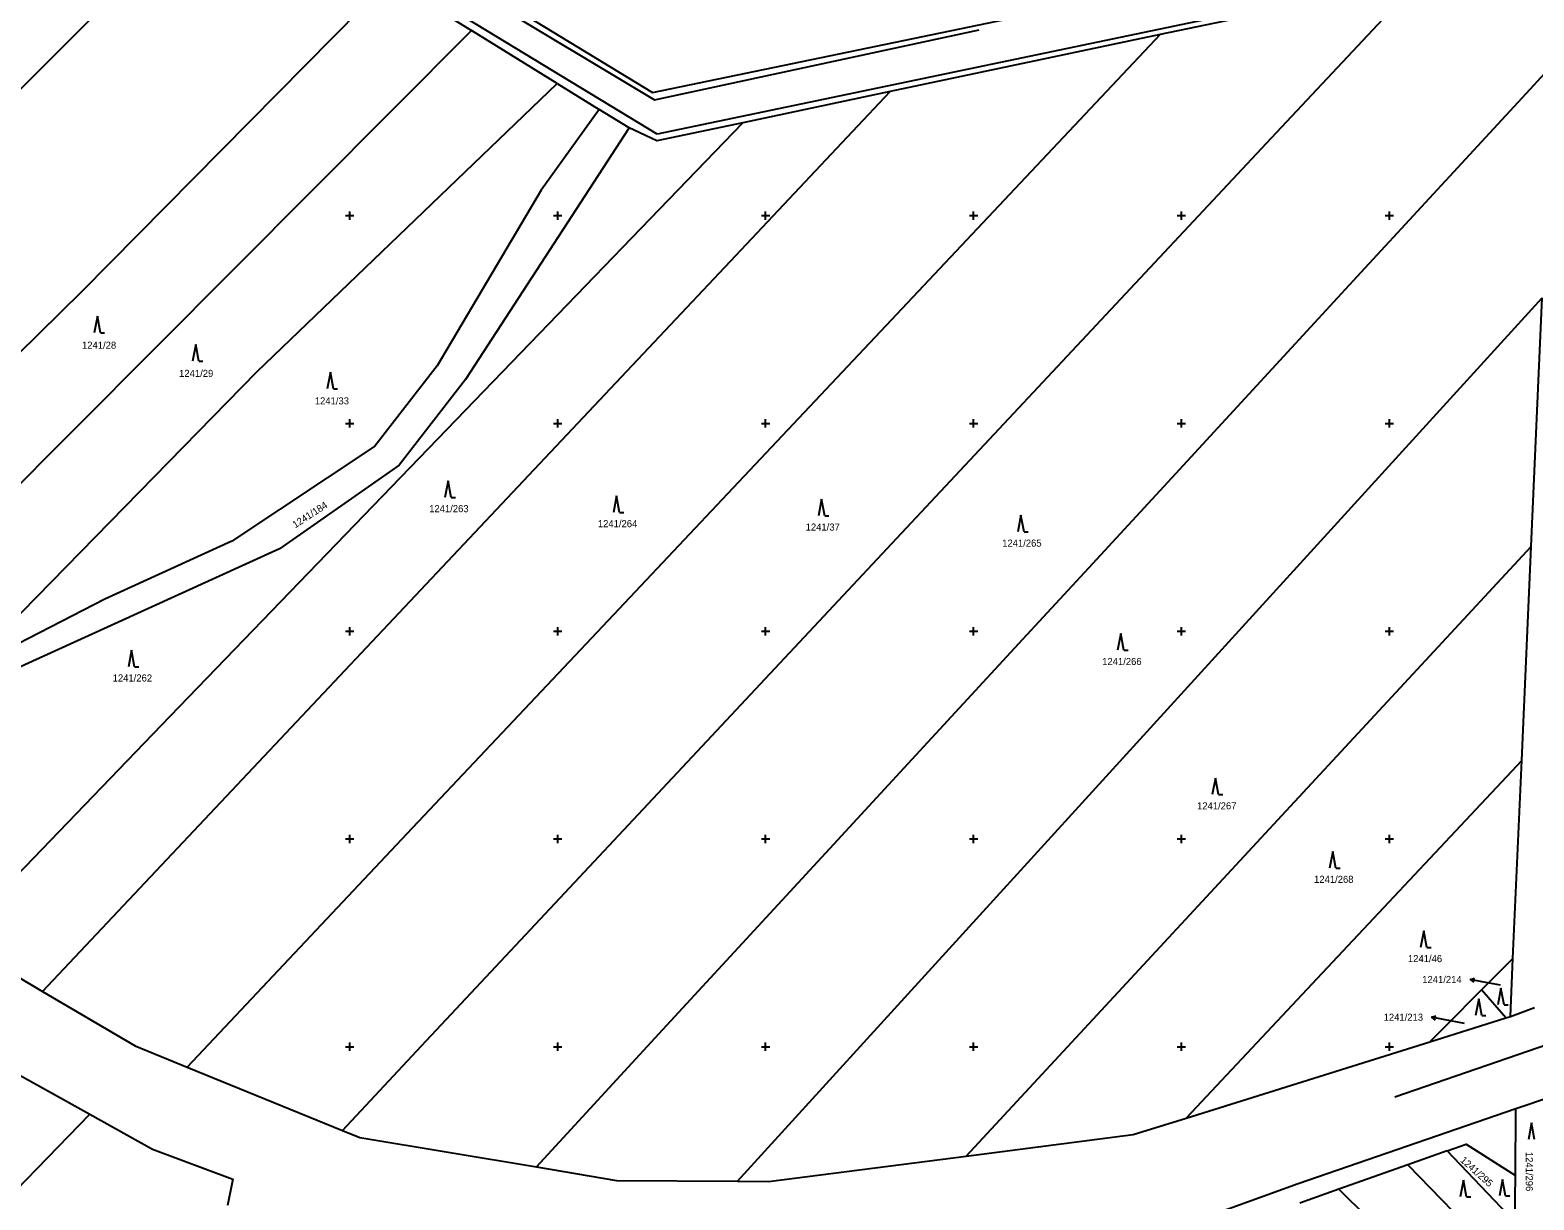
# Model space of a CAD drawing. Extents: x -776734 to -748832, y -1118122 to -976986.
# Drawn here: x -751976.9 to -751615.2, y -1114886.9 to -1114605.4 of the extents above; entities that cross this region are included whole.
import ezdxf

# ---------------------------------------------------------------- set-up
doc = ezdxf.new("R2010")
doc.units = 0
for name, color, linetype in [('KM_Hranice parcel', 7, 'Continuous'), ('KM_Parcelní čísla', 7, 'Continuous'), ('KM_Pop  PČ popisy', 7, 'Continuous'), ('KM_Vnitřní kresba', 7, 'Continuous'), ('KM_Značky kultur', 7, 'Continuous'), ('Level 61 Křížky', 7, 'Continuous'), ('OSA', 7, 'Continuous')]:
    doc.layers.add(name, color=color, linetype=linetype)

msp = doc.modelspace()

# ---------------------------------------------------------------- linework, layer by layer
at = {"layer": 'KM_Hranice parcel'}
for p, q in [((-751890.47, -1114593.24), (-751870.77, -1114605.44)), ((-751642.03, -1114593.16), (-751705.11, -1114606.47)), ((-751870.77, -1114605.44), (-752034.81, -1114770.36)), ((-751850.14, -1114618.21), (-751870.77, -1114605.44)), ((-751705.11, -1114606.47), (-751770.02, -1114620.17)), ((-751850.14, -1114618.21), (-751840, -1114624.49)), ((-751770.02, -1114620.17), (-751805.49, -1114627.66)), ((-751832.84, -1114628.92), (-751840, -1114624.49)), ((-751615.92, -1114729.62), (-751613.29, -1114669.83)), ((-751618.19, -1114781.14), (-751615.92, -1114729.62)), ((-751958.9, -1114742.29), (-751992.96, -1114759.81)), ((-751620.28, -1114828.72), (-751618.19, -1114781.14)), ((-751627.87, -1114836.32), (-751620.28, -1114828.72)), ((-751620.9, -1114842.7), (-751620.28, -1114828.72)), ((-751622.03, -1114843.06), (-751627.87, -1114836.32)), ((-751640.29, -1114848.78), (-751622.03, -1114843.06)), ((-751622.03, -1114843.06), (-751620.9, -1114842.7)), ((-751620.9, -1114842.7), (-751615.07, -1114840.52)), ((-751698.88, -1114867.14), (-751640.29, -1114848.78)), ((-751939.11, -1114854.9), (-751901.76, -1114870.11)), ((-751619.71, -1114880.94), (-751619.58, -1114864.94)), ((-751611.28, -1114862.12), (-751619.58, -1114864.94)), ((-751636.13, -1114875.06), (-751645.58, -1114878.41)), ((-751619.8, -1114892.13), (-751636.13, -1114875.06)), ((-751645.58, -1114878.41), (-751662.15, -1114884.29)), ((-751645.58, -1114878.41), (-751619.39, -1114905.36)), ((-751619.8, -1114892.13), (-751619.71, -1114880.94)), ((-751662.15, -1114884.29), (-751671.53, -1114887.62))]:
    msp.add_line(p, q, dxfattribs=at)
for points in [[(-751930.35, -1114570.59), (-752004.66, -1114645.11), (-752095.19, -1114732.79)], [(-751863.17, -1114598.48), (-751827.19, -1114620.41), (-751652.3, -1114584.09), (-751621.11, -1114577.93)], [(-752062.65, -1114764.92), (-751964.33, -1114668.21), (-751890.47, -1114593.24)], [(-751901.76, -1114870.11), (-751882.74, -1114849.78), (-751856.57, -1114821.81), (-751816.46, -1114778.95), (-751734.46, -1114691.3), (-751678.34, -1114631.33), (-751649.12, -1114600.1), (-751642.03, -1114593.16)], [(-751705.11, -1114606.47), (-751769.82, -1114675.17), (-751841.9, -1114751.7), (-751886.25, -1114798.78), (-751939.11, -1114854.9)], [(-751855.14, -1114878.92), (-751824.7, -1114845.88), (-751783.59, -1114801.27), (-751766.66, -1114782.9), (-751738.11, -1114751.92), (-751722.27, -1114734.73), (-751704.16, -1114715.09), (-751657.73, -1114664.7), (-751615.2, -1114618.55), (-751610.82, -1114613.8)], [(-751992.96, -1114759.81), (-751922.33, -1114687.6), (-751850.14, -1114618.21)], [(-751973.89, -1114836.66), (-751921.91, -1114781.47), (-751856.93, -1114712.47), (-751808.43, -1114660.96), (-751770.02, -1114620.17)], [(-751840, -1114624.49), (-751853.94, -1114643.88), (-751878.99, -1114686.19), (-751894, -1114705.47), (-751928.36, -1114728.38), (-751958.9, -1114742.29)], [(-751832.84, -1114628.92), (-751872.15, -1114689.48), (-751888.1, -1114710.05), (-751916.89, -1114730.17), (-751988.09, -1114762.56), (-752029.41, -1114785.67)], [(-751994.61, -1114823.76), (-751943.21, -1114770.46), (-751865.56, -1114689.94), (-751805.49, -1114627.66)], [(-751805.49, -1114627.66), (-751826.13, -1114632.01), (-751832.84, -1114628.92)], [(-751806.78, -1114882.34), (-751721.42, -1114788.59), (-751667.32, -1114729.17), (-751615.76, -1114672.55), (-751613.29, -1114669.83)], [(-751751.78, -1114876.29), (-751714.18, -1114835.71), (-751676.85, -1114795.4), (-751615.92, -1114729.62)], [(-751618.19, -1114781.14), (-751666.18, -1114832.29), (-751698.88, -1114867.14)], [(-751994.61, -1114823.76), (-751987.53, -1114828.61), (-751973.89, -1114836.66)], [(-751640.29, -1114848.78), (-751636.3, -1114844.78), (-751627.87, -1114836.32)], [(-751973.89, -1114836.66), (-751951.65, -1114849.8), (-751939.11, -1114854.9)], [(-751995.98, -1114846.36), (-751983.87, -1114854.34), (-751962.52, -1114866.24)], [(-751619.58, -1114864.94), (-751671.94, -1114882.94), (-751717.81, -1114899.58), (-751754.97, -1114906.02), (-751784.43, -1114907.15), (-751843.55, -1114904.34), (-751858.89, -1114907.41)], [(-752071.79, -1114978.8), (-752018.24, -1114923.64), (-751962.52, -1114866.24)], [(-751962.52, -1114866.24), (-751947.48, -1114874.63), (-751928.13, -1114881.84), (-751929.4, -1114888.2)], [(-751751.78, -1114876.29), (-751711.61, -1114871.13), (-751698.88, -1114867.14)], [(-751901.76, -1114870.11), (-751897.6, -1114871.8), (-751855.14, -1114878.92)], [(-751806.78, -1114882.34), (-751799.31, -1114882.39), (-751751.78, -1114876.29)], [(-751636.13, -1114875.06), (-751631.51, -1114873.41), (-751619.71, -1114880.94)], [(-751855.14, -1114878.92), (-751835.87, -1114882.14), (-751806.78, -1114882.34)], [(-751662.15, -1114884.29), (-751641.5, -1114904.68), (-751619.64, -1114926.27)]]:
    msp.add_lwpolyline(points, dxfattribs=at)
at = {"layer": 'KM_Pop  PČ popisy'}
for p, q in [((-751630.606, -1114833.787), (-751629.527, -1114833.487)), ((-751627.66, -1114834.36), (-751630.606, -1114833.787)), ((-751630.606, -1114833.787), (-751629.718, -1114834.47)), ((-751623.27, -1114835.19), (-751627.66, -1114834.36)), ((-751639.896, -1114842.877), (-751638.817, -1114842.577)), ((-751636.95, -1114843.45), (-751639.896, -1114842.877)), ((-751639.896, -1114842.877), (-751639.008, -1114843.56)), ((-751631.94, -1114844.43), (-751636.95, -1114843.45))]:
    msp.add_line(p, q, dxfattribs=at)
at = {"layer": 'KM_Vnitřní kresba'}
for p, q in [((-751910.92, -1114571.33), (-751826.76, -1114622.16)), ((-751617.1, -1114586.71), (-751826.11, -1114630.39)), ((-751826.11, -1114630.39), (-751889.85, -1114591.64)), ((-751826.76, -1114622.16), (-751748.67, -1114605.29))]:
    msp.add_line(p, q, dxfattribs=at)
at = {"layer": 'KM_Značky kultur'}
for p, q in [((-751960.71, -1114674.18), (-751961.46, -1114678.18)), ((-751959.96, -1114678.18), (-751960.71, -1114674.18)), ((-751959.96, -1114678.18), (-751958.964, -1114678.18)), ((-751937.06, -1114681.04), (-751937.81, -1114685.04)), ((-751936.31, -1114685.04), (-751937.06, -1114681.04)), ((-751936.31, -1114685.04), (-751935.314, -1114685.04)), ((-751904.67, -1114687.66), (-751905.42, -1114691.66)), ((-751903.92, -1114691.66), (-751904.67, -1114687.66)), ((-751903.92, -1114691.66), (-751902.924, -1114691.66)), ((-751876.36, -1114713.82), (-751877.11, -1114717.82)), ((-751875.61, -1114717.82), (-751876.36, -1114713.82)), ((-751875.61, -1114717.82), (-751874.614, -1114717.82)), ((-751835.87, -1114717.43), (-751836.62, -1114721.43)), ((-751835.12, -1114721.43), (-751835.87, -1114717.43)), ((-751786.54, -1114718.25), (-751787.29, -1114722.25)), ((-751785.79, -1114722.25), (-751786.54, -1114718.25)), ((-751835.12, -1114721.43), (-751834.124, -1114721.43)), ((-751785.79, -1114722.25), (-751784.794, -1114722.25)), ((-751738.61, -1114722.11), (-751739.36, -1114726.11)), ((-751737.86, -1114726.11), (-751738.61, -1114722.11)), ((-751737.86, -1114726.11), (-751736.864, -1114726.11)), ((-751714.6, -1114750.59), (-751715.35, -1114754.59)), ((-751713.85, -1114754.59), (-751714.6, -1114750.59)), ((-751952.49, -1114754.56), (-751953.24, -1114758.56)), ((-751951.74, -1114758.56), (-751952.49, -1114754.56)), ((-751713.85, -1114754.59), (-751712.854, -1114754.59)), ((-751951.74, -1114758.56), (-751950.744, -1114758.56)), ((-751691.83, -1114785.33), (-751692.58, -1114789.33)), ((-751691.08, -1114789.33), (-751691.83, -1114785.33)), ((-751691.08, -1114789.33), (-751690.084, -1114789.33)), ((-751663.62, -1114803.01), (-751664.37, -1114807.01)), ((-751662.87, -1114807.01), (-751663.62, -1114803.01)), ((-751662.87, -1114807.01), (-751661.874, -1114807.01)), ((-751641.74, -1114822.08), (-751642.49, -1114826.08)), ((-751640.99, -1114826.08), (-751641.74, -1114822.08)), ((-751640.99, -1114826.08), (-751639.994, -1114826.08)), ((-751623.18, -1114835.89), (-751623.93, -1114839.89)), ((-751622.43, -1114839.89), (-751623.18, -1114835.89)), ((-751628.53, -1114838.49), (-751629.28, -1114842.49)), ((-751627.78, -1114842.49), (-751628.53, -1114838.49)), ((-751622.43, -1114839.89), (-751621.434, -1114839.89)), ((-751627.78, -1114842.49), (-751626.784, -1114842.49)), ((-751615.83, -1114868.29), (-751616.58, -1114872.29)), ((-751615.08, -1114872.29), (-751615.83, -1114868.29)), ((-751632.2, -1114882.08), (-751632.95, -1114886.08)), ((-751631.45, -1114886.08), (-751632.2, -1114882.08)), ((-751622.79, -1114881.9), (-751623.54, -1114885.9)), ((-751622.04, -1114885.9), (-751622.79, -1114881.9)), ((-751631.45, -1114886.08), (-751630.454, -1114886.08)), ((-751622.04, -1114885.9), (-751621.044, -1114885.9))]:
    msp.add_line(p, q, dxfattribs=at)
at = {"layer": 'Level 61 Křížky'}
for p, q in [((-751901, -1114650), (-751899, -1114650)), ((-751900, -1114650), (-751900, -1114649)), ((-751900, -1114651), (-751900, -1114650)), ((-751851, -1114650), (-751849, -1114650)), ((-751850, -1114650), (-751850, -1114649)), ((-751850, -1114651), (-751850, -1114650)), ((-751801, -1114650), (-751799, -1114650)), ((-751800, -1114650), (-751800, -1114649)), ((-751800, -1114651), (-751800, -1114650)), ((-751751, -1114650), (-751749, -1114650)), ((-751750, -1114650), (-751750, -1114649)), ((-751750, -1114651), (-751750, -1114650)), ((-751701, -1114650), (-751699, -1114650)), ((-751700, -1114650), (-751700, -1114649)), ((-751700, -1114651), (-751700, -1114650)), ((-751651, -1114650), (-751649, -1114650)), ((-751650, -1114650), (-751650, -1114649)), ((-751650, -1114651), (-751650, -1114650)), ((-751900, -1114700), (-751900, -1114699)), ((-751850, -1114700), (-751850, -1114699)), ((-751800, -1114700), (-751800, -1114699)), ((-751750, -1114700), (-751750, -1114699)), ((-751700, -1114700), (-751700, -1114699)), ((-751650, -1114700), (-751650, -1114699)), ((-751901, -1114700), (-751899, -1114700)), ((-751900, -1114701), (-751900, -1114700)), ((-751851, -1114700), (-751849, -1114700)), ((-751850, -1114701), (-751850, -1114700)), ((-751801, -1114700), (-751799, -1114700)), ((-751800, -1114701), (-751800, -1114700)), ((-751751, -1114700), (-751749, -1114700)), ((-751750, -1114701), (-751750, -1114700)), ((-751701, -1114700), (-751699, -1114700)), ((-751700, -1114701), (-751700, -1114700)), ((-751651, -1114700), (-751649, -1114700)), ((-751650, -1114701), (-751650, -1114700)), ((-751900, -1114750), (-751900, -1114749)), ((-751850, -1114750), (-751850, -1114749)), ((-751800, -1114750), (-751800, -1114749)), ((-751750, -1114750), (-751750, -1114749)), ((-751700, -1114750), (-751700, -1114749)), ((-751650, -1114750), (-751650, -1114749)), ((-751901, -1114750), (-751899, -1114750)), ((-751900, -1114751), (-751900, -1114750)), ((-751851, -1114750), (-751849, -1114750)), ((-751850, -1114751), (-751850, -1114750)), ((-751801, -1114750), (-751799, -1114750)), ((-751800, -1114751), (-751800, -1114750)), ((-751751, -1114750), (-751749, -1114750)), ((-751750, -1114751), (-751750, -1114750)), ((-751701, -1114750), (-751699, -1114750)), ((-751700, -1114751), (-751700, -1114750)), ((-751651, -1114750), (-751649, -1114750)), ((-751650, -1114751), (-751650, -1114750)), ((-751901, -1114800), (-751899, -1114800)), ((-751900, -1114800), (-751900, -1114799)), ((-751900, -1114801), (-751900, -1114800)), ((-751851, -1114800), (-751849, -1114800)), ((-751850, -1114800), (-751850, -1114799)), ((-751850, -1114801), (-751850, -1114800)), ((-751801, -1114800), (-751799, -1114800)), ((-751800, -1114800), (-751800, -1114799)), ((-751800, -1114801), (-751800, -1114800)), ((-751751, -1114800), (-751749, -1114800)), ((-751750, -1114800), (-751750, -1114799)), ((-751750, -1114801), (-751750, -1114800)), ((-751701, -1114800), (-751699, -1114800)), ((-751700, -1114800), (-751700, -1114799)), ((-751700, -1114801), (-751700, -1114800)), ((-751651, -1114800), (-751649, -1114800)), ((-751650, -1114800), (-751650, -1114799)), ((-751650, -1114801), (-751650, -1114800)), ((-751901, -1114850), (-751899, -1114850)), ((-751900, -1114850), (-751900, -1114849)), ((-751900, -1114851), (-751900, -1114850)), ((-751851, -1114850), (-751849, -1114850)), ((-751850, -1114850), (-751850, -1114849)), ((-751850, -1114851), (-751850, -1114850)), ((-751801, -1114850), (-751799, -1114850)), ((-751800, -1114850), (-751800, -1114849)), ((-751800, -1114851), (-751800, -1114850)), ((-751751, -1114850), (-751749, -1114850)), ((-751750, -1114850), (-751750, -1114849)), ((-751750, -1114851), (-751750, -1114850)), ((-751701, -1114850), (-751699, -1114850)), ((-751700, -1114850), (-751700, -1114849)), ((-751700, -1114851), (-751700, -1114850)), ((-751651, -1114850), (-751649, -1114850)), ((-751650, -1114850), (-751650, -1114849)), ((-751650, -1114851), (-751650, -1114850))]:
    msp.add_line(p, q, dxfattribs=at)
at = {"layer": 'OSA'}
msp.add_line((-751305.6868, -1114743.777), (-751648.6661, -1114862.1099), dxfattribs=at)

# ---------------------------------------------------------------- texts
at = {"layer": 'KM_Parcelní čísla'}
for s, p in [('1241/28', (-751964.396, -1114682.04)), ('1241/29', (-751941.046, -1114688.82)), ('1241/33', (-751908.416, -1114695.44)), ('1241/263', (-751880.91, -1114721.37)), ('1241/264', (-751840.34, -1114724.98)), ('1241/37', (-751790.38, -1114725.8)), ('1241/265', (-751743.12, -1114729.66)), ('1241/266', (-751719.07, -1114758.14)), ('1241/262', (-751957.02, -1114762.11)), ('1241/267', (-751696.26, -1114792.88)), ('1241/268', (-751668.11, -1114810.56)), ('1241/46', (-751645.54, -1114829.63)), ('1241/214', (-751642.101, -1114834.65)), ('1241/213', (-751651.381, -1114843.73))]:
    msp.add_text(s, height=1.7, dxfattribs=at).set_placement(p)
for s, rotation, p in [('1241/184', 33, (-751913.116, -1114725.279)), ('1241/296', 270, (-751617.2, -1114875.29)), ('1241/295', 318, (-751633.088, -1114877.491))]:
    msp.add_text(s, height=1.7, rotation=rotation, dxfattribs=at).set_placement(p)

doc.saveas('drawing.dxf')
